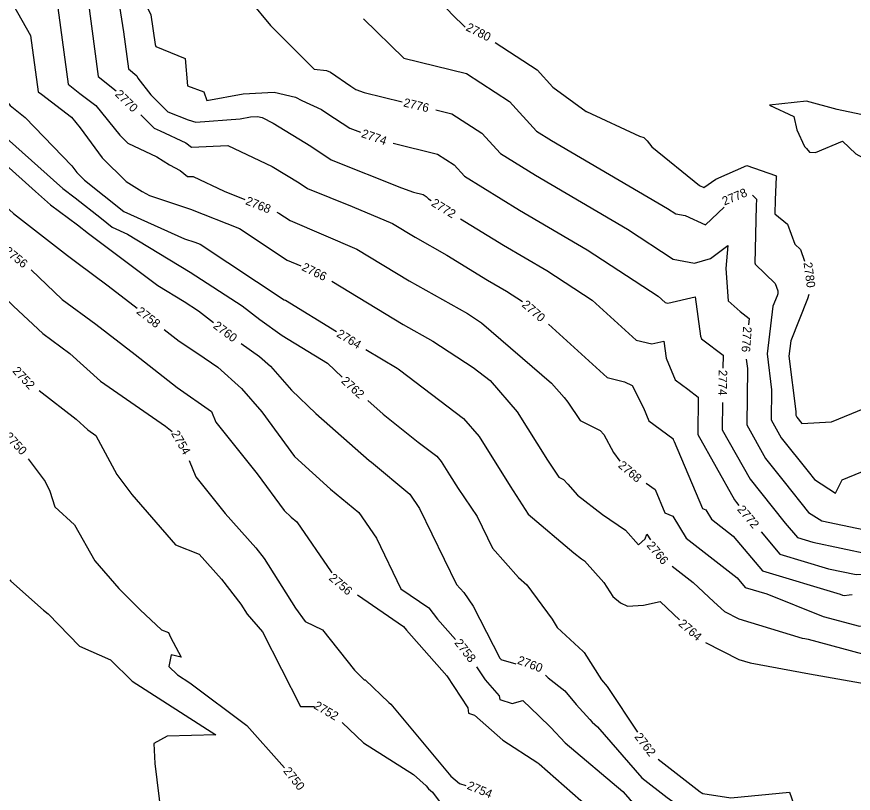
# Model space of a CAD drawing. Extents: x 1326424 to 1329294, y 1001359 to 1003823.
# Drawn here: x 1328279.2 to 1328473, y 1001626.3 to 1001806.2 of the extents above; entities that cross this region are included whole.
import ezdxf

# ---------------------------------------------------------------- set-up
doc = ezdxf.new("R2010")
doc.units = 0
doc.layers.add('Prop Rem of Exist Asph Pvmt', color=7, linetype='Continuous')
doc.layers.add('Scratch_Level_3', color=7, linetype='Continuous')

msp = doc.modelspace()

# ---------------------------------------------------------------- linework, layer by layer
at = {"layer": 'Prop Rem of Exist Asph Pvmt'}
for points in [[(1328384.39, 1001836.75), (1328382.86, 1001837.45), (1328379.28, 1001838.62), (1328378.17, 1001839.06), (1328376.3, 1001839.83), (1328365.43, 1001842.87), (1328359.5, 1001844.75), (1328351.54, 1001851.6), (1328350.85, 1001852.21), (1328349.66, 1001852.84), (1328349.96, 1001851.07), (1328350.39, 1001851.03), (1328350.4, 1001850.6), (1328355.71, 1001842.78), (1328356.42, 1001838.1), (1328356.82, 1001834.15), (1328365.92, 1001822.4), (1328367.8, 1001820.36), (1328367.99, 1001820.09), (1328380.08, 1001806.75), (1328383.13, 1001803.75)], [(1328390.12, 1001800.19), (1328399.8, 1001793.87), (1328403.46, 1001789.89), (1328411.19, 1001784.26), (1328411.25, 1001784.22), (1328423.53, 1001778.49), (1328424.55, 1001778.24), (1328425.31, 1001777.4), (1328426.38, 1001776.01), (1328437.41, 1001767.05), (1328438.46, 1001766.66), (1328441.19, 1001768.55), (1328448.39, 1001771.74), (1328455, 1001769.37), (1328455.18, 1001769.32), (1328455.21, 1001769.29), (1328455.25, 1001769.24), (1328455.22, 1001769.12), (1328454.94, 1001763.74), (1328454.88, 1001760.53), (1328457.84, 1001758.1), (1328459.48, 1001753.53), (1328460.83, 1001752.23), (1328461.72, 1001749.58)], [(1328248.02, 1001798.84), (1328249.27, 1001796.93), (1328249.99, 1001796.31), (1328250.81, 1001795.82), (1328267.44, 1001780.12), (1328283.61, 1001765.72), (1328287.06, 1001762.63), (1328293.33, 1001757.94), (1328295.84, 1001755.96), (1328311.94, 1001743.9), (1328318.02, 1001740.2), (1328321.32, 1001738.05), (1328324.86, 1001735.33)], [(1328462.77, 1001741.85), (1328462.41, 1001740.87), (1328458.57, 1001731.11), (1328458.15, 1001727.59), (1328459.73, 1001714.71), (1328459.72, 1001713.91), (1328459.99, 1001713.43), (1328461.16, 1001711.97), (1328467.97, 1001712.35), (1328475.73, 1001715.5), (1328477.83, 1001717.15), (1328483.41, 1001719.24), (1328501.3, 1001718.64), (1328510.51, 1001722.73), (1328512.3, 1001723.27), (1328512.74, 1001723.46), (1328522.14, 1001727.52), (1328526.06, 1001729.35)], [(1328331.25, 1001730.52), (1328335.49, 1001727.49), (1328338.02, 1001725.22), (1328342.86, 1001719.66), (1328348.52, 1001714.28), (1328360.92, 1001703.41), (1328361.46, 1001702.97), (1328370.34, 1001695.57), (1328372.57, 1001692.24), (1328381.15, 1001674.65), (1328382.79, 1001672.81), (1328384.95, 1001669.66), (1328391.19, 1001657.62), (1328391.38, 1001657.33), (1328391.41, 1001657.29), (1328394.9, 1001656.25)], [(1328401.73, 1001653.66), (1328402.35, 1001653.07), (1328406.22, 1001650.02), (1328408.88, 1001646.89), (1328411.98, 1001643.36), (1328412.53, 1001642.77), (1328413.76, 1001641.72), (1328424.09, 1001629.87), (1328429.96, 1001625.3), (1328433.61, 1001622.68), (1328441.21, 1001618.84), (1328455.43, 1001616.6), (1328459.12, 1001614.84), (1328459.96, 1001614.32), (1328461.78, 1001614.14), (1328468.79, 1001613.66), (1328482.83, 1001612.28), (1328487.21, 1001612.44)]]:
    msp.add_lwpolyline(points, dxfattribs=at)
at = {"layer": 'Scratch_Level_3'}
for points in [[(1328276.83, 1001882.27), (1328280.9, 1001873.46), (1328284.68, 1001864.82), (1328288.06, 1001857.84), (1328286.54, 1001853.71), (1328290.49, 1001838.16), (1328289.01, 1001833.14), (1328289.36, 1001832.13), (1328293.99, 1001822.12), (1328294.99, 1001815.76), (1328298.14, 1001792.36), (1328302.27, 1001789.05)], [(1328313.27, 1001857.06), (1328313.62, 1001852.83), (1328317.07, 1001843.95), (1328316.34, 1001834.08), (1328315.87, 1001830.84), (1328316.23, 1001827.58), (1328316.64, 1001827.19), (1328317.81, 1001821.84), (1328322.27, 1001819.8), (1328328.78, 1001815.49), (1328333.13, 1001810.02), (1328338.04, 1001804.18), (1328343.58, 1001798.58), (1328348.17, 1001794.02), (1328351.04, 1001793.71), (1328351.9, 1001793.32), (1328356.62, 1001790.11), (1328357.79, 1001789.35), (1328359.75, 1001788.63), (1328368.53, 1001786.5)], [(1328283.39, 1001839.96), (1328285.29, 1001832.47), (1328285.05, 1001831.66), (1328285.11, 1001831.49), (1328285.86, 1001829.88), (1328286.02, 1001828.85), (1328291.17, 1001790.59), (1328293.89, 1001788.41), (1328297.6, 1001785.59), (1328303.11, 1001778.78), (1328305, 1001776.92), (1328311.72, 1001773.73), (1328314.62, 1001771.91), (1328317.08, 1001770.55), (1328318.83, 1001769.15), (1328320.08, 1001769.21), (1328327.29, 1001765.79), (1328332.05, 1001763.88)], [(1328300.41, 1001838.52), (1328299.48, 1001835.65), (1328299.29, 1001834.38), (1328299.32, 1001834.15), (1328302.25, 1001831.33), (1328305.32, 1001817.28), (1328310.27, 1001806.6), (1328311.34, 1001799.74), (1328311.5, 1001799.27), (1328318.24, 1001796.47), (1328318.78, 1001790.2), (1328322.6, 1001788.76), (1328323.27, 1001786.74), (1328331.73, 1001788.34), (1328338.88, 1001788.69), (1328343.86, 1001787.54), (1328345.31, 1001786.77), (1328349.82, 1001784.73), (1328351.1, 1001783.85), (1328356.44, 1001780.35), (1328358.88, 1001779.47)], [(1328302.19, 1001814), (1328303.96, 1001802.67), (1328305.11, 1001794.13), (1328307.1, 1001792.53), (1328307.31, 1001791.93), (1328310.29, 1001788.12), (1328314.27, 1001784.18), (1328318.97, 1001782.33), (1328320.74, 1001781.73), (1328331, 1001782.54), (1328333.42, 1001783), (1328335.01, 1001783.08), (1328336.11, 1001782.82), (1328338.63, 1001781.49), (1328347.35, 1001776.19), (1328352.11, 1001773.04), (1328368.35, 1001766.57), (1328371.16, 1001765.55), (1328373.37, 1001765.02), (1328374.13, 1001764.53), (1328374.6, 1001764.01), (1328375.26, 1001763.6)], [(1328276.4, 1001812.58), (1328282.45, 1001801.85), (1328284.2, 1001788.82), (1328284.94, 1001788.23), (1328291.91, 1001782.94), (1328293.93, 1001780.44), (1328299.06, 1001773.5), (1328304.57, 1001768.05), (1328308.29, 1001765.71), (1328310, 1001764.76), (1328319.51, 1001761.64), (1328330.85, 1001757.09), (1328341.9, 1001749.8), (1328345.06, 1001748.45)], [(1328359.59, 1001805.73), (1328368.89, 1001796.57), (1328383.41, 1001793.04), (1328393.38, 1001786.53), (1328399.66, 1001779.7), (1328403.15, 1001777.55), (1328430.04, 1001761.78), (1328431.97, 1001760.52), (1328434.09, 1001760.11), (1328438.78, 1001758.01), (1328443.1, 1001762.09)], [(1328232.05, 1001803.52), (1328237.77, 1001795.08), (1328240, 1001792.46), (1328252.86, 1001779.78), (1328256.95, 1001776.01), (1328267.23, 1001768.12), (1328272.82, 1001765.66), (1328278.52, 1001760.58), (1328290.98, 1001750.88), (1328293.2, 1001749.23), (1328300.46, 1001743.81), (1328307.11, 1001738.64)], [(1328273.2, 1001791.16), (1328277.68, 1001785.61), (1328281.23, 1001782.82), (1328292.04, 1001771.67), (1328293.19, 1001770.12), (1328294.97, 1001768.35), (1328304.09, 1001761.05), (1328318.09, 1001754.76), (1328320.51, 1001753.97), (1328321.74, 1001753.47), (1328341.21, 1001740.63), (1328341.48, 1001740.51), (1328353.32, 1001733.3)], [(1328475.39, 1001783.55), (1328474.76, 1001783.53), (1328469.33, 1001784.72), (1328462.2, 1001786.6), (1328453.61, 1001785.68), (1328459.25, 1001783.07), (1328460, 1001779.98), (1328461.73, 1001776.11), (1328462.23, 1001775.68), (1328462.89, 1001774.78), (1328464.3, 1001774.72), (1328470.53, 1001777.34), (1328473.65, 1001774.45), (1328476.91, 1001772.67), (1328482.27, 1001769.89), (1328484.72, 1001768.64), (1328490.81, 1001768.56), (1328495.75, 1001766.08), (1328497.96, 1001765.75), (1328500.22, 1001764.25), (1328500.95, 1001765.17), (1328510.71, 1001763.17), (1328508.43, 1001762.1), (1328514.05, 1001757.53)], [(1328376.3, 1001784.62), (1328380.07, 1001783.7), (1328386.97, 1001779.2), (1328391.31, 1001774.47), (1328399.44, 1001769.45), (1328420.71, 1001756.98), (1328431.31, 1001750.06), (1328436.3, 1001749.11), (1328439.99, 1001750.18), (1328443.96, 1001753.17), (1328443.5, 1001747.84), (1328444.07, 1001740.35), (1328446.81, 1001737.91), (1328448.96, 1001736.26), (1328448.78, 1001734.81)], [(1328307.96, 1001783.46), (1328311.05, 1001780.4), (1328312.44, 1001779.74), (1328318.43, 1001776.98), (1328319.71, 1001775.96), (1328328.14, 1001776.37), (1328338.44, 1001771.47), (1328344.65, 1001767.69), (1328346.59, 1001766.41), (1328356.98, 1001762.26), (1328366.31, 1001758.26), (1328371.51, 1001755.09), (1328378.92, 1001750.97), (1328388.32, 1001745.17), (1328392.69, 1001742.61), (1328396.4, 1001740.19)], [(1328273.76, 1001780.84), (1328276.85, 1001778.09), (1328289.9, 1001766.4), (1328292.79, 1001764.24), (1328298.9, 1001759.43), (1328301.36, 1001757.46), (1328304.94, 1001755.85), (1328319.41, 1001747.03), (1328331.44, 1001739.19), (1328335.53, 1001736.06), (1328340.71, 1001732.36), (1328351.2, 1001725.96), (1328354.67, 1001722.67)], [(1328242.6, 1001777.54), (1328254.37, 1001767), (1328255.2, 1001766.23), (1328255.75, 1001765.8), (1328256.83, 1001764.72), (1328265.57, 1001752.25), (1328267, 1001749.27), (1328271.93, 1001745.74), (1328278.52, 1001739.16), (1328285.27, 1001732.78), (1328291.51, 1001728.18), (1328298.66, 1001721.73), (1328313.73, 1001711.34), (1328315.28, 1001710.14)], [(1328366.44, 1001776.86), (1328376.72, 1001774.36), (1328380.55, 1001771.86), (1328382.95, 1001769.24), (1328395.74, 1001761.36), (1328411.37, 1001752.19), (1328427.83, 1001741.45), (1328429.48, 1001739.96), (1328430.07, 1001739.81), (1328436.42, 1001741.33), (1328437.64, 1001732.17), (1328437.88, 1001731.6), (1328438.21, 1001731.36), (1328442.89, 1001727.76), (1328442.85, 1001724.8)], [(1328449.72, 1001764.82), (1328450.61, 1001763.93), (1328450.53, 1001762.39), (1328450.24, 1001749.05), (1328450.31, 1001749), (1328450.34, 1001748.9), (1328454.98, 1001744.41), (1328455.55, 1001742.72), (1328455.54, 1001742.01), (1328455.38, 1001741.56), (1328454.41, 1001739.11), (1328453.09, 1001728.1), (1328454.13, 1001719.72), (1328454.04, 1001712.78), (1328456.37, 1001708.64), (1328462.59, 1001700.83), (1328464.08, 1001698.96), (1328468.91, 1001695.83), (1328470.47, 1001698.9), (1328479.16, 1001702.42), (1328483.61, 1001705.94), (1328486.22, 1001706.91), (1328487.19, 1001706.88)], [(1328339.47, 1001760.9), (1328339.96, 1001760.71), (1328342.59, 1001758.98), (1328358.03, 1001752.34), (1328370.12, 1001744.97), (1328383.65, 1001737.45), (1328386.95, 1001735.3), (1328403.16, 1001721.33), (1328406.04, 1001718), (1328406.94, 1001716.88), (1328409.79, 1001712.68), (1328414.4, 1001710.32), (1328415.25, 1001709.38), (1328417.53, 1001705.27), (1328418.99, 1001703.26)], [(1328382.07, 1001759.4), (1328392.03, 1001753.26), (1328402.03, 1001747.4), (1328412.56, 1001740.53), (1328422.75, 1001731.28), (1328426.4, 1001730.38), (1328429.13, 1001731.04), (1328429.66, 1001727.1), (1328431.78, 1001722.07), (1328434.74, 1001719.91), (1328437.11, 1001718.09), (1328437, 1001709.38), (1328445.52, 1001694.27), (1328446.01, 1001693.65), (1328446.56, 1001692.96)], [(1328282.58, 1001747.52), (1328289.78, 1001740.71), (1328297.53, 1001735), (1328306.64, 1001727.92), (1328316.38, 1001720.31), (1328324.33, 1001714.75), (1328325.38, 1001712.28), (1328334.97, 1001700.26), (1328341.17, 1001691.77), (1328342.85, 1001690.26), (1328344.16, 1001689.17), (1328352.05, 1001677.57), (1328352.22, 1001677.33)], [(1328352.22, 1001744.93), (1328368.73, 1001734.86), (1328375.63, 1001731.02), (1328384.97, 1001724.92), (1328388.93, 1001721.92), (1328395.21, 1001714.64), (1328402.19, 1001703.47), (1328404.86, 1001699.53), (1328405.91, 1001698.99), (1328406.89, 1001697.9), (1328409.19, 1001695.33), (1328414.94, 1001690.9), (1328420.31, 1001687.21), (1328423.28, 1001683.88), (1328424.86, 1001685.27), (1328425.25, 1001686.31), (1328426.05, 1001684.98)], [(1328313.42, 1001733.73), (1328316.89, 1001731.04), (1328321.21, 1001728.18), (1328325.84, 1001725.03), (1328331.34, 1001720.09), (1328336.04, 1001714.68), (1328343.63, 1001704.29), (1328351.97, 1001696.77), (1328358.53, 1001691.33), (1328362.59, 1001685.36), (1328368.26, 1001673.64), (1328374.69, 1001669.27), (1328376.72, 1001666.62), (1328380.89, 1001661.89)], [(1328402.42, 1001734.95), (1328416.01, 1001722.61), (1328420.01, 1001721.63), (1328421.85, 1001720.75), (1328424.41, 1001715.57), (1328425.69, 1001712.54), (1328431.28, 1001708.46), (1328431.32, 1001708.43), (1328431.32, 1001708.25), (1328431.57, 1001707.82), (1328438.13, 1001692.27), (1328438.9, 1001691.96), (1328440.22, 1001689.76), (1328445.24, 1001685.86), (1328452.05, 1001677.81), (1328469.98, 1001672.43), (1328470.57, 1001672.19), (1328470.95, 1001672.09), (1328472.08, 1001672.3), (1328472.78, 1001672.34)], [(1328360.15, 1001729.13), (1328367.35, 1001724.74), (1328367.6, 1001724.6), (1328367.95, 1001724.37), (1328382.73, 1001713.13), (1328386.38, 1001708.91), (1328393.53, 1001697.46), (1328397.74, 1001690.95), (1328408.34, 1001681.97), (1328410.1, 1001680.62), (1328410.79, 1001680.14), (1328415.29, 1001675.1), (1328417.36, 1001671.86), (1328419.1, 1001670.42), (1328420.71, 1001669.62), (1328424.44, 1001669.85), (1328428.28, 1001670.69), (1328431.42, 1001667.77), (1328432.81, 1001666.48)], [(1328448.26, 1001726.86), (1328448.52, 1001724.73), (1328448.36, 1001711.65), (1328452.75, 1001703.85), (1328457.06, 1001698.43), (1328462.7, 1001691.36), (1328465.75, 1001689.38), (1328478.64, 1001686.7), (1328478.91, 1001686.87), (1328479.99, 1001687.77), (1328482.19, 1001689.86), (1328487.32, 1001693.51), (1328489.33, 1001694.8), (1328490.09, 1001695.35), (1328493.22, 1001696.99), (1328516.18, 1001707.2), (1328516.19, 1001707.2)], [(1328284.45, 1001719.62), (1328293, 1001712.93), (1328295.72, 1001710.47), (1328297.58, 1001709.19), (1328302.44, 1001700.12), (1328305.93, 1001695.54), (1328316.02, 1001683.88), (1328321.53, 1001681.65), (1328326.68, 1001675.9), (1328331.14, 1001670.14), (1328332.65, 1001667.77), (1328336.14, 1001663.7), (1328344.99, 1001646.41), (1328348.2, 1001646.41)], [(1328360.55, 1001717.26), (1328364.17, 1001714.09), (1328372.24, 1001707.62), (1328376.54, 1001704.35), (1328377.54, 1001703.19), (1328379.51, 1001700.04), (1328381.54, 1001696.89), (1328385.9, 1001690.4), (1328389.48, 1001683.04), (1328395.48, 1001676.32), (1328397.42, 1001674.6), (1328403.27, 1001666.61), (1328404.42, 1001664.69), (1328410.45, 1001659.11), (1328410.7, 1001658.87), (1328414.74, 1001652.54), (1328416.04, 1001651.01), (1328416.22, 1001650.81), (1328423.02, 1001640.48)], [(1328442.76, 1001716.8), (1328442.68, 1001710.52), (1328449.13, 1001699.06), (1328451.54, 1001696.04), (1328457.26, 1001688.86), (1328460.09, 1001685.51), (1328463.68, 1001684.43), (1328476.79, 1001681.7), (1328484.1, 1001682.02), (1328485.13, 1001682.4), (1328492.31, 1001684.56), (1328493.87, 1001685.11), (1328495.71, 1001685.9), (1328501, 1001689.46), (1328519.94, 1001696.06)], [(1328281.92, 1001703.79), (1328285.83, 1001698.53), (1328286.89, 1001696.31), (1328288.08, 1001692.67), (1328292.66, 1001688.51), (1328297.3, 1001680.13), (1328302.87, 1001673.75), (1328307.82, 1001668.82), (1328312.76, 1001664.16), (1328314.4, 1001663.51), (1328314.9, 1001662.49), (1328317.36, 1001657.81), (1328315, 1001658.33), (1328314.45, 1001655.68), (1328316.49, 1001653.7), (1328319.33, 1001651.87), (1328332.56, 1001641.99), (1328340.63, 1001632.85), (1328341.26, 1001632.18)], [(1328319.15, 1001703.36), (1328320.73, 1001699.61), (1328327.55, 1001691.07), (1328334.61, 1001683.18), (1328336.53, 1001680.71), (1328343.84, 1001669.17), (1328346.03, 1001666.11), (1328350.06, 1001664.17), (1328357.53, 1001654.84), (1328359.77, 1001652.61), (1328359.99, 1001652.59), (1328365.47, 1001647.35), (1328365.9, 1001646.95), (1328379.78, 1001630.27), (1328381.8, 1001628.57), (1328383.27, 1001628.11)], [(1328451.7, 1001686.83), (1328456.07, 1001681.66), (1328467.32, 1001678.29), (1328473.72, 1001676.95), (1328482.34, 1001677.32), (1328488.75, 1001677.72), (1328494.72, 1001679.84), (1328503.14, 1001683.45), (1328504.54, 1001684.01), (1328506.16, 1001684.54), (1328521.53, 1001690.29), (1328524.06, 1001691.17), (1328525.27, 1001691.91), (1328539.8, 1001696.63), (1328540.57, 1001696.92), (1328541.85, 1001698.22), (1328544.04, 1001699.88)], [(1328425.03, 1001698.13), (1328427.14, 1001696.65), (1328429.42, 1001691.26), (1328431.24, 1001690.52), (1328434.34, 1001685.36), (1328446.14, 1001676.19), (1328448.03, 1001673.95), (1328453.01, 1001672.46), (1328466.07, 1001667.24), (1328474.5, 1001664.98), (1328495.5, 1001668.86), (1328496.24, 1001669.03), (1328497.69, 1001669.79), (1328506.87, 1001673.43), (1328509.73, 1001674.37), (1328510.77, 1001674.65)], [(1328431.07, 1001678.93), (1328435.92, 1001675.16), (1328440.74, 1001670.68), (1328443.23, 1001668.37), (1328446.5, 1001666.7), (1328461.23, 1001662.25), (1328461.8, 1001662.14), (1328462.59, 1001662), (1328478.04, 1001657.86), (1328488.45, 1001659.78), (1328495.5, 1001661.41), (1328506.58, 1001667.23), (1328508.32, 1001667.85), (1328510.48, 1001668.78), (1328522.96, 1001672.11)], [(1328277.62, 1001675.77), (1328277.88, 1001675.41), (1328285.42, 1001668.7), (1328286.52, 1001667.89), (1328293.8, 1001660.36), (1328300.96, 1001657.21), (1328306, 1001652.28), (1328325.36, 1001639.86), (1328314.11, 1001639.53), (1328311.03, 1001637.86), (1328311.27, 1001633.2), (1328313.72, 1001613.03)], [(1328358.16, 1001672.23), (1328368.88, 1001664.93), (1328369.55, 1001664.06), (1328378.87, 1001653.49), (1328383.73, 1001646.1), (1328383.94, 1001644.82), (1328385.26, 1001644.41), (1328391.86, 1001638.57), (1328399.98, 1001633.32), (1328400.06, 1001633.24), (1328400.09, 1001633.21), (1328400.24, 1001633.09), (1328409.92, 1001624.65), (1328419.29, 1001618.97), (1328420.74, 1001618.37), (1328425.26, 1001615.12), (1328434.68, 1001610.35)], [(1328438.83, 1001661.26), (1328446.54, 1001657.32), (1328449.15, 1001656.53), (1328462.89, 1001653.93), (1328480, 1001650.99), (1328481.4, 1001650.39), (1328482.13, 1001650.4), (1328495.21, 1001652.36), (1328497.43, 1001653.47), (1328512.73, 1001657.55), (1328514.5, 1001658.91), (1328528.64, 1001664.11), (1328532.14, 1001666.97), (1328533.63, 1001667.69)], [(1328385.79, 1001655.6), (1328387.79, 1001652.61), (1328390.98, 1001648.88), (1328391.14, 1001647.99), (1328394.04, 1001647.07), (1328396.46, 1001647.78), (1328400.2, 1001644.23), (1328403, 1001641.52), (1328406.31, 1001637.99), (1328419.66, 1001626.71), (1328421.38, 1001624.74), (1328422.36, 1001623.98), (1328429.44, 1001618.9), (1328444.18, 1001611.44), (1328452.73, 1001610.09), (1328457.65, 1001607.75), (1328460.75, 1001607.12), (1328468.01, 1001606.34)], [(1328354.62, 1001642.66), (1328359.61, 1001637.96), (1328371.19, 1001630.66), (1328374.08, 1001628.01), (1328374.66, 1001627.32), (1328375.56, 1001626.56), (1328387.21, 1001610.88), (1328392.62, 1001608.89), (1328413.84, 1001598.81), (1328414.18, 1001598.5), (1328436.59, 1001594.4), (1328437.83, 1001593.7)], [(1328427.85, 1001634.19), (1328437.57, 1001626.62), (1328437.79, 1001626.47), (1328438.23, 1001626.24), (1328444.69, 1001625.22), (1328458.31, 1001626.58), (1328459.85, 1001622.18), (1328460.68, 1001621.87), (1328464.7, 1001621.47), (1328464.89, 1001621.45), (1328492.56, 1001618.75), (1328495.01, 1001618.83), (1328497.31, 1001619.35), (1328513.57, 1001624.56), (1328515.9, 1001625.86), (1328518.38, 1001629.68)]]:
    msp.add_lwpolyline(points, dxfattribs=at)

# ---------------------------------------------------------------- texts
at = {"layer": 'Prop Rem of Exist Asph Pvmt'}
for s, rotation, p in [('2780', 333.0125, (1328383.13, 1001803.11)), ('2780', 277.7102, (1328461.52, 1001749.2)), ('2760', 323.0192, (1328324.59, 1001734.25)), ('2760', 339.2423, (1328395.05, 1001656.37))]:
    msp.add_text(s, height=2, rotation=rotation, dxfattribs=at).set_placement(p)
at = {"layer": 'Scratch_Level_3'}
for s, rotation, p in [('2770', 315.5183, (1328301.86, 1001788.07)), ('2776', 346.3471, (1328368.7, 1001785.43)), ('2774', 340.9224, (1328358.93, 1001778.34)), ('2778', 22.4471, (1328443.17, 1001762.43)), ('2768', 338.1648, (1328332.08, 1001762.79)), ('2772', 328.3456, (1328375.1, 1001762.53)), ('2756', 320.8385, (1328276.13, 1001751.59)), ('2766', 333.8346, (1328345.09, 1001747.54)), ('2770', 318.9794, (1328396.1, 1001739.23)), ('2758', 322.1357, (1328306.82, 1001737.6)), ('2764', 328.6295, (1328353.17, 1001732.22)), ('2776', 266.2212, (1328447.54, 1001734.48)), ('2752', 313.0358, (1328278.12, 1001724.02)), ('2774', 269.3163, (1328441.85, 1001724.39)), ('2762', 317.4149, (1328354.26, 1001721.59)), ('2754', 299.74, (1328314.95, 1001709.66)), ('2750', 312.9663, (1328276.27, 1001708.84)), ('2768', 319.6629, (1328418.41, 1001702)), ('2772', 309.9934, (1328446.05, 1001691.99)), ('2766', 309.6897, (1328425.06, 1001683.66)), ('2756', 319.3207, (1328351.4, 1001675.91)), ('2764', 319.0904, (1328432.39, 1001665.34)), ('2758', 307.899, (1328380.55, 1001661.11)), ('2752', 329.6662, (1328347.89, 1001646.08)), ('2762', 307.5405, (1328422.25, 1001639.36)), ('2750', 308.4784, (1328340.88, 1001631.43)), ('2754', 337.3401, (1328383.4, 1001627.37))]:
    msp.add_text(s, height=2, rotation=rotation, dxfattribs=at).set_placement(p)

doc.saveas('drawing.dxf')
